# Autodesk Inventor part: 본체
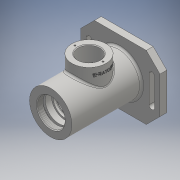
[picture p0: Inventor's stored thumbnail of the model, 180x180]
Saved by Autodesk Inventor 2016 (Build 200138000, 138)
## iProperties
Created: 2017-10
Part Number: 본체
Material: 일반
Document SubType Name: Modeling
Designer: USER
Density: 1 g/cm^3
Appearance: 기본값
Author: USER
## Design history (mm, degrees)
sketch "스케치1"
  geometry: C1 r 31 at (0, 0); 1 further point
  constraints: 1 centre point, 1 coincident
  dimensions: "d0" = 62 diameter of C1
extrude "돌출1" new body sketch "스케치1" distance "d1" = 102; taper "d2" = 0 deg
sketch "스케치2"
  geometry: L1 (-58, -47)-(58, -47); L2 (58, -47)-(58, 47); L3 (58, 47)-(-58, 47); L4 (-58, 47)-(-58, -47); C1 r 31 at (0, 0) reference; 2 further points
  constraints: 8 end point, 2 midpoint, 2 parallel, 1 horizontal, 1 horizontal alignment, 1 perpendicular, 1 vertical alignment
  dimensions: "d5" = 116 distance of L1.start L1.end; "d6" = 94 distance of L3.end L1.start
extrude "돌출2" join sketch "스케치2" distance "d7" = 10; taper "d8" = 0 deg
sketch "스케치3"
  geometry: C1 r 35 at (0, 0); 1 further point
  constraints: 1 centre point, 1 coincident
  dimensions: "d9" = 70 diameter of C1
extrude "돌출3" join sketch "스케치3" distance "d10" = 3; taper "d11" = 0 deg
node "작업 평면1"
sketch "스케치4"
  geometry: C1 r 25 at (0, 56); 1 further point
  constraints: 1 centre point, 1 vertical alignment
  dimensions: "d13" = 50 diameter of C1; "d14" = 56 distance of point (0, 0) C1.centre
extrude "돌출4" join sketch "스케치4" distance "d15" = 31.25; taper "d16" = 0 deg
sketch "스케치5"
  geometry: L1 (0, 0)-(128.633, 0); L2 (115, -35)-(115, 35) reference; L3 (101, 14.022)-(101, 12.904); L4 (101, 12.904)-(100.3, 12.5); L5 (100.3, 12.5)-(94, 12.5); L6 (93.7, 12.2)-(93.7, 10); L7 (93.7, 10)-(91, 10); L8 (91, 10)-(91, 13.5); L9 (88, 16.5)-(86, 16.5); L10 (86, 16.5)-(86, 17.2); L11 (85.7, 17.5)-(76, 17.5); L12 (75, 18.5)-(75, 23); L13 (72, 26)-(40, 26); L14 (37, 23)-(37, 18.5); L15 (102.818, 16.779)-(115, 22); L16 (36, 17.5)-(26, 17.5); L17 (26, 17.5)-(26, 18.5); L18 (26, 18.5)-(24.25, 18.5); L19 (21, 17.5)-(21, 20); L20 (21, 20)-(12, 20); L21 (12, 20)-(12, 24); L22 (12, 24)-(9, 24); L23 (9, 24)-(9, 0); L24 (21, 17.5)-(24.25, 17.5); L25 (24.25, 17.5)-(24.25, 18.5); L26 (0, 31)-(0, -31) reference; L27 (9, 0)-(115, 0); L28 (115, 22)-(115, 0); L29 (37, 18.5)-(36, 17.5); L30 (76, 17.5)-(75, 18.5); A1 r 0.3 centre (94, 12.2) between (94, 12.5) and (93.7, 12.2); A2 r 0.3 centre (85.7, 17.2) between (86, 17.2) and (85.7, 17.5); A3 r 3 centre (104, 14.022) between (102.818, 16.779) and (101, 14.022); A4 r 3 centre (88, 13.5) between (91, 13.5) and (88, 16.5); A5 r 3 centre (72, 23) between (75, 23) and (72, 26); A6 r 3 centre (40, 23) between (40, 26) and (37, 23); 8 further points
  constraints: 56 end point, 18 point on line, 17 perpendicular, 12 point on circle, 12 tangent, 6 centre point, 4 equal radius, 3 horizontal, 1 collinear, 1 horizontal alignment, 1 midpoint, 1 parallel
  dimensions: "d17" = 30 deg angle of L5 L4; "d20" = 32 diameter of point (101, 16) L1; "d22" = 44 diameter of L15.end L1; "d24" = 52 diameter of L13 L1; "d25" = 35 diameter of L11 L1; "d26" = 33 diameter of L9 L1; "d27" = 38 distance of point (75, 26) point (37, 26); "d28" = 5 distance between parallel lines of L8 L10; "d30" = 2.7 distance of L6.end L7.end; "d31" = 20 diameter of L7 L1; "d32" = 25 diameter of L5 L1; "d33" = 11 distance of point (86, 17.5) point (75, 17.5); "d34" = 35 diameter of L16 L1; "d35" = 11 distance of point (37, 17.5) L16.end; "d36" = 3 distance of L21.end L22.end; "d37" = 48 diameter of L22 L1; "d38" = 40 diameter of L20 L1; "d39" = 35 diameter of L24 L1; "d40" = 37 diameter of L18 L1; "d41" = 1.75 distance of L17.end L18.end; "d42" = 12 distance between parallel lines of L21 L26; "d43" = 21 distance between parallel lines of L26 L19; "d48" = 24 distance between parallel lines of L2 L8; "d49" = 0.3 radius of A1; "d50" = 3 radius of A3; "d51" = 1 distance of L14.end point (37, 17.5); "d52" = 1 distance of L16.start point (37, 17.5) (= d51); "d53" = 1 distance of L11.end point (75, 17.5) (= d51); "d54" = 1 distance of L12.start point (75, 17.5) (= d53); "d97" = 7.3 distance between parallel lines of L3 L6; "d98" = 0.7 horizontal distance of L3.end L4.end
revolve "회전1" sketch "스케치5" stored, may be unused: angle "d44" = 90 deg
sketch "스케치6"
  geometry: C1 r 31 at (0, 0) reference; 2 further points
  constraints: 1 coincident
hole "구멍1" sketch "스케치6" at (0, 0) diameter "d55" = 40.376; stored, may be unused: countersink angle "d59" = 90 deg, drill point angle "d61" = 0 deg; dims "d56" = 84, "d57" = 4, "d58" = 2, "d60" = 9
sketch "스케치7"
  geometry: C1 r 25 at (0, 0) reference; C2 r 16 at (0, 0); 1 further point
  constraints: 1 centre point, 1 coincident
  dimensions: "d62" = 32 diameter of C2
extrude "돌출5" cut sketch "스케치7" distance "d63" = 39.25; taper "d64" = 0 deg
sketch "스케치8"
  geometry: C1 r 16 at (0, 0) reference; 3 further points
  constraints: 3 horizontal alignment
  dimensions: "d65" = 41 distance of point (20.5, 0) point (-20.5, 0); "d66" = 20.5 distance of point (-20.5, 0) C1.centre
hole "구멍2" sketch "스케치8" at (20.5, 0), (-20.5, 0) diameter "d67" = 2.459; stored, may be unused: countersink angle "d71" = 90 deg, drill point angle "d73" = 118 deg; dims "d68" = 6, "d69" = 4, "d70" = 2, "d72" = 8
node "작업 평면2"
sketch "스케치9"
  geometry: L1 (0, 31)-(0, -31) reference; L2 (31, 47)-(81, 47) reference; 2 further points
  constraints: 1 other
  dimensions: "d75" = 56 distance from line of point (56, 37) L1; "d76" = 10 distance from line of point (56, 37) L2
feature "엠보싱1" sketch "스케치9" dims "d77" = 0.5, "d78" = 0
chamfer "모따기1" distance "d79" = 20; stored, may be unused: second distance "d80" = 2, angle "d81" = 45 deg
sketch "스케치10"
  geometry: L1 (46, 20)-(46, -20); L2 (42, 20)-(42, -20); L3 (50, -20)-(50, 20); L4 (-46, 20)-(-46, -20); L5 (-50, 20)-(-50, -20); L6 (-42, -20)-(-42, 20); A1 r 4 centre (46, 20) between (50, 20) and (42, 20); A2 r 4 centre (46, -20) between (42, -20) and (50, -20); A3 r 4 centre (-46, 20) between (-42, 20) and (-50, 20); A4 r 4 centre (-46, -20) between (-50, -20) and (-42, -20); 3 further points
  constraints: 16 end point, 8 point on circle, 8 tangent, 4 centre point, 3 parallel, 2 horizontal alignment, 2 midpoint, 1 vertical
  dimensions: "d82" = 46 distance from line of point (0, 0) L1; "d83" = 46 distance of point (-46, 0) point (0, 0); "d84" = 4 radius of A2; "d85" = 4 radius of A4; "d86" = 40 distance of L4.start L4.end; "d87" = 40 distance of L1.start L1.end
extrude "돌출6" cut sketch "스케치10" distance "d88" = 39.25; taper "d89" = 0 deg
fillet "모깎기1" dims "d90" = 3
chamfer "모따기2" distance "d91" = 1; stored, may be unused: second distance "d92" = 2, angle "d93" = 45 deg
chamfer "모따기3" distance "d94" = 1; stored, may be unused: second distance "d95" = 2, angle "d96" = 45 deg
node "솔리드1"
node "투영된 루프1"
other parameters: "d12" = 47, "d74" = 25
